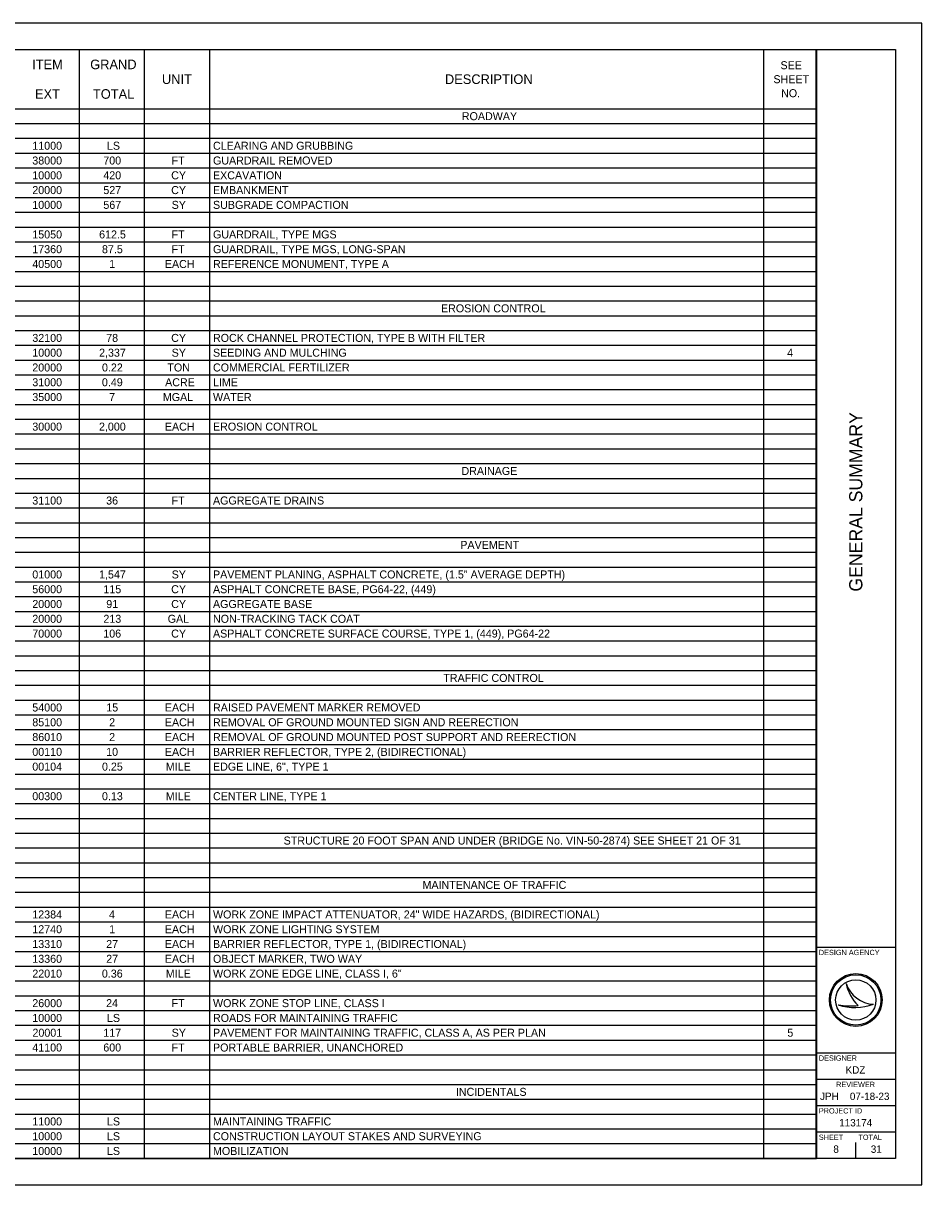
# Model space of a CAD drawing. Extents: x 0 to 34, y 0 to 22.
# Drawn here: x 16.98 to 34, y 0 to 22 of the extents above; entities that cross this region are included whole.
import ezdxf

# ---------------------------------------------------------------- set-up
doc = ezdxf.new("R2010")
doc.units = 0
for name, color, linetype in [('Default', 7, 'Continuous'), ('SH_Border', 7, 'Continuous'), ('SH_Cut_Line', 7, 'Continuous'), ('SH_Data', 7, 'Continuous')]:
    doc.layers.add(name, color=color, linetype=linetype)

msp = doc.modelspace()

# ---------------------------------------------------------------- linework, layer by layer
at = {"layer": 'Default'}
for p, q in [((1.5, 21.5), (32.004, 21.5)), ((18.036, 21.5), (18.036, 0.5)), ((19.272, 21.5), (19.272, 0.5)), ((20.507, 21.5), (20.507, 0.5)), ((30.999, 21.5), (30.999, 0.5)), ((32.004, 21.5), (32.004, 0.5)), ((1.5, 20.38), (32.004, 20.38)), ((1.5, 20.1), (32.004, 20.1)), ((1.5, 19.82), (32.004, 19.82)), ((1.5, 19.54), (32.004, 19.54)), ((1.5, 19.26), (32.004, 19.26)), ((1.5, 18.98), (32.004, 18.98)), ((1.5, 18.7), (32.004, 18.7)), ((1.5, 18.42), (32.004, 18.42)), ((1.5, 18.14), (32.004, 18.14)), ((1.5, 17.86), (32.004, 17.86)), ((1.5, 17.58), (32.004, 17.58)), ((1.5, 17.3), (32.004, 17.3)), ((1.5, 17.02), (32.004, 17.02)), ((1.5, 16.74), (32.004, 16.74)), ((1.5, 16.46), (32.004, 16.46)), ((1.5, 16.18), (32.004, 16.18)), ((1.5, 15.9), (32.004, 15.9)), ((1.5, 15.62), (32.004, 15.62)), ((1.5, 15.34), (32.004, 15.34)), ((1.5, 15.06), (32.004, 15.06)), ((1.5, 14.78), (32.004, 14.78)), ((1.5, 14.5), (32.004, 14.5)), ((1.5, 14.22), (32.004, 14.22)), ((1.5, 13.94), (32.004, 13.94)), ((1.5, 13.66), (32.004, 13.66)), ((1.5, 13.38), (32.004, 13.38)), ((1.5, 13.1), (32.004, 13.1)), ((1.5, 12.82), (32.004, 12.82)), ((1.5, 12.54), (32.004, 12.54)), ((1.5, 12.26), (32.004, 12.26)), ((1.5, 11.98), (32.004, 11.98)), ((1.5, 11.7), (32.004, 11.7)), ((1.5, 11.42), (32.004, 11.42)), ((1.5, 11.14), (32.004, 11.14)), ((1.5, 10.86), (32.004, 10.86)), ((1.5, 10.58), (32.004, 10.58)), ((1.5, 10.3), (32.004, 10.3)), ((1.5, 10.02), (32.004, 10.02)), ((1.5, 9.74), (32.004, 9.74)), ((1.5, 9.46), (32.004, 9.46)), ((1.5, 9.18), (32.004, 9.18)), ((1.5, 8.9), (32.004, 8.9)), ((1.5, 8.62), (32.004, 8.62)), ((1.5, 8.34), (32.004, 8.34)), ((1.5, 8.06), (32.004, 8.06)), ((1.5, 7.78), (32.004, 7.78)), ((1.5, 7.5), (32.004, 7.5)), ((1.5, 7.22), (32.004, 7.22)), ((1.5, 6.94), (32.004, 6.94)), ((1.5, 6.66), (32.004, 6.66)), ((1.5, 6.38), (32.004, 6.38)), ((1.5, 6.1), (32.004, 6.1)), ((1.5, 5.82), (32.004, 5.82)), ((1.5, 5.54), (32.004, 5.54)), ((1.5, 5.26), (32.004, 5.26)), ((1.5, 4.98), (32.004, 4.98)), ((1.5, 4.7), (32.004, 4.7)), ((1.5, 4.42), (32.004, 4.42)), ((1.5, 4.14), (32.004, 4.14)), ((1.5, 3.86), (32.004, 3.86)), ((1.5, 3.58), (32.004, 3.58)), ((1.5, 3.3), (32.004, 3.3)), ((1.5, 3.02), (32.004, 3.02)), ((1.5, 2.74), (32.004, 2.74)), ((1.5, 2.46), (32.004, 2.46)), ((1.5, 2.18), (32.004, 2.18)), ((1.5, 1.9), (32.004, 1.9)), ((1.5, 1.62), (32.004, 1.62)), ((1.5, 1.34), (32.004, 1.34)), ((1.5, 1.06), (32.004, 1.06)), ((1.5, 0.78), (32.004, 0.78)), ((1.5, 0.5), (32.004, 0.5))]:
    msp.add_line(p, q, dxfattribs=at)
at = {"layer": 'SH_Border'}
for p, q in [((32, 0.5), (32, 21.5)), ((32, 4.5), (33.5, 4.5)), ((32, 2.5), (33.5, 2.5)), ((32, 2), (33.5, 2)), ((32, 1.5), (33.5, 1.5)), ((32, 1), (33.5, 1))]:
    msp.add_line(p, q, dxfattribs=at)
msp.add_lwpolyline([(1.5, 21.5), (33.5, 21.5), (33.5, 0.5), (1.5, 0.5)], close=True, dxfattribs=at)
at = {"layer": 'SH_Cut_Line'}
msp.add_lwpolyline([(0, 0), (34, 0), (34, 22), (0, 22)], close=True, dxfattribs=at)
at = {"layer": 'SH_Data'}
for p, q in [((32.567, 3.81), (32.567, 3.81)), ((32.417, 3.41), (32.417, 3.41)), ((32.75, 3.5), (32.75, 3.5)), ((33.087, 3.419), (33.087, 3.419)), ((32.375, 0.675), (32.375, 0.675)), ((32.75, 0.5), (32.75, 0.8))]:
    msp.add_line(p, q, dxfattribs=at)
for radius in [0.5, 0.477, 0.477, 0.382]:
    msp.add_circle((32.75, 3.5), radius, dxfattribs=at)
for centre, radius, start, end in [((33.116, 3.998), 0.58, 198.9257, 198.9319), ((33.347, 3.97), 0.796, 191.6379, 191.6421), ((33.116, 3.998), 0.58, 198.9319, 267.1657), ((33.347, 3.97), 0.796, 191.6421, 226.0947), ((32.739, 4.37), 1.013, 251.4576, 290.0832), ((32.648, 4.654), 1.266, 259.4964, 259.4995), ((32.739, 4.37), 1.013, 251.4527, 251.4576), ((32.648, 4.654), 1.266, 259.4995, 276.6672)]:
    msp.add_arc(centre, radius, start, end, dxfattribs=at)

# ---------------------------------------------------------------- texts
at = {"layer": 'Default'}
for s, height, p in [('ITEM', 0.1818, (17.147, 21.129)), ('GRAND', 0.1818, (18.247, 21.129)), ('SEE ', 0.1515, (31.324, 21.129)), ('UNIT', 0.1818, (19.606, 20.849)), ('DESCRIPTION', 0.18184, (24.967, 20.849)), ('SHEET ', 0.1515, (31.19, 20.864)), ('EXT', 0.1818, (17.201, 20.569)), ('TOTAL', 0.1818, (18.299, 20.569)), ('NO.', 0.1515, (31.335, 20.599)), ('ROADWAY', 0.1515, (25.287, 20.164)), ('11000', 0.1515, (17.15, 19.604)), ('LS', 0.1515, (18.564, 19.604)), ('CLEARING AND GRUBBING', 0.15153, (20.573, 19.604)), ('38000', 0.1515, (17.15, 19.324)), ('700', 0.1515, (18.495, 19.324)), ('FT', 0.1515, (19.789, 19.324)), ('GUARDRAIL REMOVED', 0.15153, (20.573, 19.324)), ('10000', 0.1515, (17.15, 19.044)), ('420', 0.1515, (18.495, 19.044)), ('CY', 0.1515, (19.781, 19.044)), ('EXCAVATION', 0.1515, (20.573, 19.044)), ('20000', 0.1515, (17.15, 18.764)), ('527', 0.1515, (18.496, 18.764)), ('CY', 0.1515, (19.781, 18.764)), ('EMBANKMENT', 0.1515, (20.573, 18.764)), ('10000', 0.1515, (17.15, 18.484)), ('567', 0.1515, (18.496, 18.484)), ('SY', 0.1515, (19.79, 18.484)), ('SUBGRADE COMPACTION', 0.15153, (20.573, 18.484)), ('15050', 0.1515, (17.15, 17.924)), ('612.5', 0.1515, (18.416, 17.924)), ('FT', 0.1515, (19.789, 17.924)), ('GUARDRAIL, TYPE MGS', 0.15153, (20.573, 17.924)), ('17360', 0.1515, (17.15, 17.644)), ('87.5', 0.1515, (18.47, 17.644)), ('FT', 0.1515, (19.789, 17.644)), ('GUARDRAIL, TYPE MGS, LONG-SPAN', 0.15153, (20.573, 17.644)), ('40500', 0.1515, (17.15, 17.364)), ('1', 0.152, (18.606, 17.364)), ('EACH', 0.1515, (19.661, 17.364)), ('REFERENCE MONUMENT, TYPE A', 0.15153, (20.573, 17.364)), ('EROSION CONTROL', 0.15153, (24.892, 16.524)), ('32100', 0.1515, (17.15, 15.964)), ('78', 0.1515, (18.55, 15.964)), ('CY', 0.1515, (19.781, 15.964)), ('ROCK CHANNEL PROTECTION, TYPE B WITH FILTER', 0.15153, (20.573, 15.964)), ('10000', 0.1515, (17.15, 15.684)), ('2,337', 0.1515, (18.415, 15.684)), ('SY', 0.1515, (19.79, 15.684)), ('SEEDING AND MULCHING', 0.15153, (20.573, 15.684)), ('4', 0.152, (31.45, 15.684)), ('20000', 0.1515, (17.15, 15.404)), ('0.22', 0.1515, (18.47, 15.404)), ('TON', 0.1515, (19.709, 15.404)), ('COMMERCIAL FERTILIZER', 0.15153, (20.573, 15.404)), ('31000', 0.1515, (17.15, 15.124)), ('0.49', 0.1515, (18.469, 15.124)), ('ACRE', 0.1515, (19.666, 15.124)), ('LIME', 0.1515, (20.573, 15.124)), ('35000', 0.1515, (17.15, 14.844)), ('7', 0.152, (18.605, 14.844)), ('MGAL', 0.1515, (19.623, 14.844)), ('WATER', 0.1515, (20.573, 14.844)), ('30000', 0.1515, (17.15, 14.284)), ('2,000', 0.1515, (18.413, 14.284)), ('EACH', 0.1515, (19.661, 14.284)), ('EROSION CONTROL', 0.15153, (20.573, 14.284)), ('DRAINAGE', 0.1515, (25.28, 13.444)), ('31100', 0.1515, (17.15, 12.884)), ('36', 0.1515, (18.549, 12.884)), ('FT', 0.1515, (19.789, 12.884)), ('AGGREGATE DRAINS', 0.15153, (20.573, 12.884)), ('PAVEMENT', 0.1515, (25.258, 12.044)), ('01000', 0.1515, (17.15, 11.484)), ('1,547', 0.1515, (18.415, 11.484)), ('SY', 0.1515, (19.79, 11.484)), ('PAVEMENT PLANING, ASPHALT CONCRETE, (1.5" AVERAGE DEPTH)', 0.15153, (20.573, 11.484)), ('56000', 0.1515, (17.15, 11.204)), ('115', 0.1515, (18.497, 11.204)), ('CY', 0.1515, (19.781, 11.204)), ('ASPHALT CONCRETE BASE, PG64-22, (449)', 0.15153, (20.573, 11.204)), ('20000', 0.1515, (17.15, 10.924)), ('91', 0.1515, (18.551, 10.924)), ('CY', 0.1515, (19.781, 10.924)), ('AGGREGATE BASE', 0.15153, (20.573, 10.924)), ('20000', 0.1515, (17.15, 10.644)), ('213', 0.1515, (18.497, 10.644)), ('GAL', 0.1515, (19.715, 10.644)), ('NON-TRACKING TACK COAT', 0.15153, (20.573, 10.644)), ('70000', 0.1515, (17.15, 10.364)), ('106', 0.1515, (18.495, 10.364)), ('CY', 0.1515, (19.781, 10.364)), ('ASPHALT CONCRETE SURFACE COURSE, TYPE 1, (449), PG64-22', 0.15153, (20.573, 10.364)), ('TRAFFIC CONTROL', 0.15153, (24.936, 9.524)), ('54000', 0.1515, (17.15, 8.964)), ('15', 0.1515, (18.552, 8.964)), ('EACH', 0.1515, (19.661, 8.964)), ('RAISED PAVEMENT MARKER REMOVED', 0.15153, (20.573, 8.964)), ('85100', 0.1515, (17.15, 8.684)), ('2', 0.152, (18.606, 8.684)), ('EACH', 0.1515, (19.661, 8.684)), ('REMOVAL OF GROUND MOUNTED SIGN AND REERECTION', 0.15153, (20.573, 8.684)), ('86010', 0.1515, (17.15, 8.404)), ('2', 0.152, (18.606, 8.404)), ('EACH', 0.1515, (19.661, 8.404)), ('REMOVAL OF GROUND MOUNTED POST SUPPORT AND REERECTION', 0.15153, (20.573, 8.404)), ('00110', 0.1515, (17.15, 8.124)), ('10', 0.1515, (18.549, 8.124)), ('EACH', 0.1515, (19.661, 8.124)), ('BARRIER REFLECTOR, TYPE 2, (BIDIRECTIONAL)', 0.15153, (20.573, 8.124)), ('00104', 0.1515, (17.15, 7.844)), ('0.25', 0.1515, (18.47, 7.844)), ('MILE', 0.1515, (19.679, 7.844)), ('EDGE LINE, 6", TYPE 1', 0.15153, (20.573, 7.844)), ('00300', 0.1515, (17.15, 7.284)), ('0.13', 0.1515, (18.47, 7.284)), ('MILE', 0.1515, (19.679, 7.284)), ('CENTER LINE, TYPE 1', 0.15153, (20.573, 7.284)), ('STRUCTURE 20 FOOT SPAN AND UNDER (BRIDGE No. VIN-50-2874) SEE SHEET 21 OF 31', 0.15153, (21.911, 6.444)), ('MAINTENANCE OF TRAFFIC', 0.15153, (24.542, 5.604)), ('12384', 0.1515, (17.15, 5.044)), ('4', 0.152, (18.603, 5.044)), ('EACH', 0.1515, (19.661, 5.044)), ('WORK ZONE IMPACT ATTENUATOR, 24" WIDE HAZARDS, (BIDIRECTIONAL)', 0.15153, (20.573, 5.044)), ('12740', 0.1515, (17.15, 4.764)), ('1', 0.152, (18.606, 4.764)), ('EACH', 0.1515, (19.661, 4.764)), ('WORK ZONE LIGHTING SYSTEM', 0.15153, (20.573, 4.764)), ('13310', 0.1515, (17.15, 4.484)), ('27', 0.1515, (18.55, 4.484)), ('EACH', 0.1515, (19.661, 4.484)), ('BARRIER REFLECTOR, TYPE 1, (BIDIRECTIONAL)', 0.15153, (20.573, 4.484)), ('13360', 0.1515, (17.15, 4.204)), ('27', 0.1515, (18.55, 4.204)), ('EACH', 0.1515, (19.661, 4.204)), ('OBJECT MARKER, TWO WAY', 0.15153, (20.573, 4.204)), ('22010', 0.1515, (17.15, 3.924)), ('0.36', 0.1515, (18.468, 3.924)), ('MILE', 0.1515, (19.679, 3.924)), ('WORK ZONE EDGE LINE, CLASS I, 6"', 0.15153, (20.573, 3.924)), ('26000', 0.1515, (17.15, 3.364)), ('24', 0.1515, (18.548, 3.364)), ('FT', 0.1515, (19.789, 3.364)), ('WORK ZONE STOP LINE, CLASS I', 0.15153, (20.573, 3.364)), ('10000', 0.1515, (17.15, 3.084)), ('LS', 0.1515, (18.564, 3.084)), ('ROADS FOR MAINTAINING TRAFFIC', 0.15153, (20.573, 3.084)), ('20001', 0.1515, (17.153, 2.804)), ('117', 0.1515, (18.496, 2.804)), ('SY', 0.1515, (19.79, 2.804)), ('PAVEMENT FOR MAINTAINING TRAFFIC, CLASS A, AS PER PLAN', 0.15153, (20.573, 2.804)), ('5', 0.152, (31.453, 2.804)), ('41100', 0.1515, (17.15, 2.524)), ('600', 0.1515, (18.495, 2.524)), ('FT', 0.1515, (19.789, 2.524)), ('PORTABLE BARRIER, UNANCHORED', 0.15153, (20.573, 2.524)), ('INCIDENTALS', 0.15153, (25.174, 1.684)), ('11000', 0.1515, (17.15, 1.124)), ('LS', 0.1515, (18.564, 1.124)), ('MAINTAINING TRAFFIC', 0.15153, (20.573, 1.124)), ('10000', 0.1515, (17.15, 0.844)), ('LS', 0.1515, (18.564, 0.844)), ('CONSTRUCTION LAYOUT STAKES AND SURVEYING', 0.15153, (20.573, 0.844)), ('10000', 0.1515, (17.15, 0.564)), ('LS', 0.1515, (18.564, 0.564)), ('MOBILIZATION', 0.15153, (20.573, 0.564))]:
    msp.add_text(s, height=height, dxfattribs=at).set_placement(p)
at = {"layer": 'SH_Data'}
msp.add_text('GENERAL SUMMARY', height=0.25, rotation=90, dxfattribs=at).set_placement((32.875, 11.235))
for s, height, p in [('DESIGN AGENCY', 0.1, (32.05, 4.35)), ('DESIGNER', 0.1, (32.05, 2.35)), ('KDZ', 0.14, (32.557, 2.105)), ('REVIEWER', 0.1, (32.378, 1.85)), ('JPH', 0.14, (32.073, 1.605)), ('07-18-23', 0.14, (32.638, 1.605)), ('PROJECT ID', 0.1, (32.05, 1.35)), ('113174', 0.14, (32.436, 1.105)), ('SHEET', 0.1, (32.05, 0.85)), ('TOTAL', 0.1, (32.8, 0.85)), ('8', 0.14, (32.325, 0.605)), ('31', 0.14, (33.034, 0.605))]:
    msp.add_text(s, height=height, dxfattribs=at).set_placement(p)

doc.saveas('drawing.dxf')
